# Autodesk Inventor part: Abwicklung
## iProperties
Author: WN
Created: 2003-03
Part Number: Abwicklung
Material: Standard
Document SubType Name: Blech
Designer: WN
Control State: 0
Master: False
Checked Out: False
PropertySet Name: Design Tracking Control
Shininess: 20.0
Angle Display Precision: 2
Document Length Units: 11269
Document Angle Units: 11283
Document Time Units: 11279
Document Mass Units: 11290
Document Length Units Precision: 3
Document Angle Units Precision: 2
Compacted: True
PropertySet Name: _Private Model Information
Density: 0.0
Volumn: 0.0
Area: 0.0
PropertySet Name: Model Information
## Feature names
1. Platte18
2. Platte19
3. Biegung15
4. Platte20
5. Biegung16
6. Platte21
7. Biegung17
8. Platte22
9. Biegung18
10. Platte23
11. Biegung19
12. Platte24
13. Biegung20
14. ExtrusionAbwicklung1
